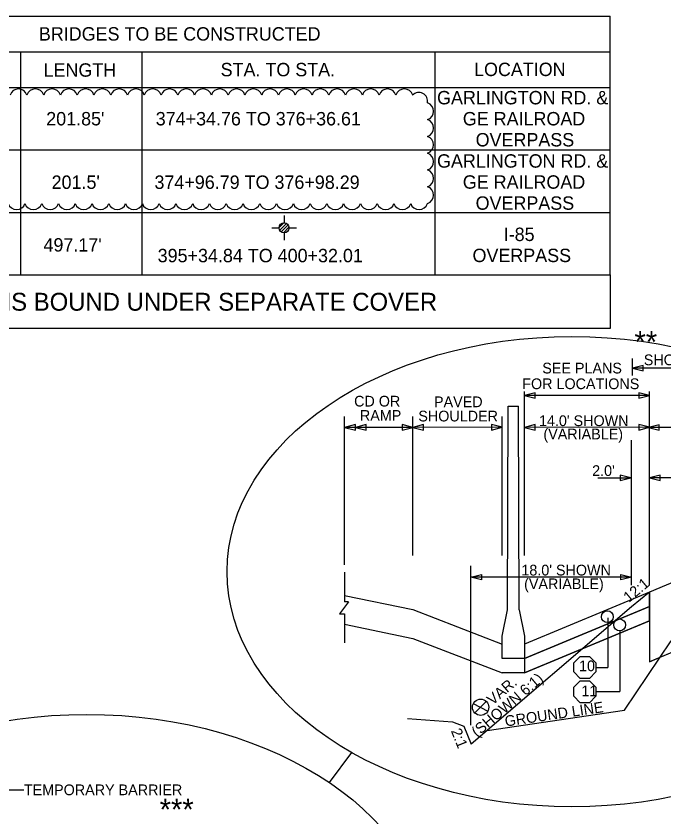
# Model space of a CAD drawing. Extents: x 4832 to 5477, y 4935 to 5220.
# Drawn here: x 5049.2 to 5121.8, y 5127.7 to 5217.4 of the extents above; entities that cross this region are included whole.
import ezdxf

# ---------------------------------------------------------------- set-up
doc = ezdxf.new("R2010")
doc.units = 0
for name, color, linetype in [('Level 2', 7, 'Continuous'), ('Level 3', 7, 'Continuous'), ('Level 42', 7, 'Continuous'), ('RD_EX_SU_Pole', 7, 'Continuous'), ('RD_QTY_Milling', 7, 'Continuous'), ('RD_QTY_Surf_Course', 7, 'Continuous'), ('RD_SHT_TX', 7, 'Continuous'), ('RD_SHT_Typical', 7, 'Continuous'), ('RD_TX_TypSect', 7, 'Continuous'), ('RD_XS_ExGround', 7, 'Continuous'), ('RD_XS_PaveShd', 7, 'Continuous'), ('TERMINATOR', 7, 'Continuous'), ('typical_on', 7, 'Continuous')]:
    doc.layers.add(name, color=color, linetype=linetype)

# ---------------------------------------------------------------- blocks, each defined once
blk = doc.blocks.new('AH')
at = {"layer": 'TERMINATOR'}
blk.add_lwpolyline([(-6, 1.5), (0, 0), (-6, -1.5)], close=True, dxfattribs=at)
blk = doc.blocks.new('SUE_TFP')
at = {"layer": 'RD_EX_SU_Pole'}
for p, q in [((0, 5.5), (0, 2.22)), ((-2.21, 0.13), (-0.13, 2.21)), ((-1.96, -1.03), (1.03, 1.96)), ((-1.31, -1.79), (1.79, 1.31)), ((-0.3, -2.2), (2.2, 0.3)), ((2.22, 0), (5.53, 0.01)), ((-5.53, -0.01), (-2.22, 0)), ((0, -2.22), (0, -5.5))]:
    blk.add_line(p, q, dxfattribs=at)
blk.add_circle((0, 0), 2.22, dxfattribs=at)

msp = doc.modelspace()

# ---------------------------------------------------------------- linework, layer by layer
at = {"layer": 'Level 2'}
for p, q in [((5104.248, 5150.93), (5104.326, 5173.731)), ((5104.326, 5173.731), (5105.471, 5173.731)), ((5105.548, 5150.93), (5105.471, 5173.731)), ((5103.649, 5147.966), (5104.248, 5150.93)), ((5105.548, 5150.93), (5106.148, 5147.967)), ((5103.649, 5145.464), (5103.649, 5147.966)), ((5106.148, 5147.967), (5106.148, 5145.464)), ((5106.148, 5145.464), (5103.649, 5145.464)), ((5106.148, 5143.857), (5103.649, 5143.857))]:
    msp.add_line(p, q, dxfattribs=at)
at = {"layer": 'Level 3'}
for p, q in [((5018.153, 5217.416), (5115.753, 5217.416)), ((5115.753, 5188.416), (5115.753, 5217.416)), ((5018.153, 5213.416), (5115.753, 5213.416)), ((5049.753, 5188.416), (5049.753, 5213.416)), ((5063.353, 5188.416), (5063.353, 5213.416)), ((5096.153, 5188.416), (5096.153, 5213.416)), ((5018.153, 5209.416), (5115.753, 5209.416)), ((5018.153, 5202.416), (5115.753, 5202.416)), ((5018.153, 5195.416), (5115.753, 5195.416)), ((5018.153, 5188.416), (5115.753, 5188.416)), ((5031.753, 5188.416), (5115.753, 5188.416))]:
    msp.add_line(p, q, dxfattribs=at)
at = {"layer": 'Level 42'}
msp.add_lwpolyline([(5018.153, 5188.416), (5115.753, 5188.416), (5115.753, 5182.416), (5018.153, 5182.416)], close=True, dxfattribs=at)
at = {"layer": 'RD_QTY_Milling'}
for p, q in [((5120.142, 5152.902), (5106.148, 5147.071)), ((5120.143, 5151.295), (5120.142, 5152.902)), ((5120.143, 5151.295), (5115.472, 5149.349)), ((5120.143, 5149.689), (5120.143, 5151.295)), ((5115.472, 5149.349), (5106.148, 5145.464)), ((5106.148, 5147.071), (5106.148, 5145.464)), ((5106.148, 5145.464), (5106.148, 5143.857))]:
    msp.add_line(p, q, dxfattribs=at)
for points in [[(5106.148, 5145.464), (5115.472, 5149.349), (5120.143, 5151.295)], [(5106.148, 5143.857), (5116.81, 5148.3), (5120.143, 5149.689)]]:
    msp.add_lwpolyline(points, dxfattribs=at)
at = {"layer": 'RD_QTY_Surf_Course'}
msp.add_line((5086.013, 5152.529), (5093.653, 5150.942), dxfattribs=at)
at = {"layer": 'RD_SHT_TX'}
for centre, radius, start, end in [((5049.495, 5208.266), 0.985, 17.5, 162.5), ((5051.373, 5208.266), 0.985, 17.5, 162.5), ((5053.251, 5208.266), 0.985, 17.5, 162.5), ((5055.129, 5208.266), 0.985, 17.5, 162.5), ((5057.007, 5208.266), 0.985, 17.5, 162.5), ((5058.885, 5208.266), 0.985, 17.5, 162.5), ((5060.764, 5208.266), 0.985, 17.5, 162.5), ((5062.642, 5208.266), 0.985, 17.5, 162.5), ((5064.52, 5208.266), 0.985, 17.5, 162.5), ((5066.398, 5208.266), 0.985, 17.5, 162.5), ((5068.276, 5208.266), 0.985, 17.5, 162.5), ((5070.154, 5208.266), 0.985, 17.5, 162.5), ((5072.032, 5208.266), 0.985, 17.5, 162.5), ((5073.91, 5208.266), 0.985, 17.5, 162.5), ((5075.788, 5208.266), 0.985, 17.5, 162.5), ((5077.666, 5208.266), 0.985, 17.5, 162.5), ((5079.544, 5208.266), 0.985, 17.5, 162.5), ((5081.422, 5208.266), 0.985, 17.5, 162.5), ((5083.3, 5208.266), 0.985, 17.5, 162.5), ((5085.178, 5208.266), 0.985, 17.5, 162.5), ((5087.056, 5208.266), 0.985, 17.5, 162.5), ((5088.935, 5208.266), 0.985, 17.5, 162.5), ((5090.813, 5208.266), 0.985, 17.5, 162.5), ((5092.691, 5208.266), 0.985, 17.5, 162.5), ((5094.323, 5207.863), 0.984, 349.79926, 134.79926), ((5094.996, 5206.75), 0.985, 287.5, 72.5), ((5094.996, 5204.872), 0.985, 287.5, 72.5), ((5094.996, 5202.994), 0.985, 287.5, 72.5), ((5094.996, 5201.116), 0.985, 287.5, 72.5), ((5094.996, 5199.237), 0.985, 287.5, 72.5), ((5094.996, 5197.359), 0.985, 287.5, 72.5), ((5049.279, 5196.716), 0.985, 197.5, 342.5), ((5051.157, 5196.716), 0.985, 197.5, 342.5), ((5053.036, 5196.716), 0.985, 197.5, 342.5), ((5054.914, 5196.716), 0.985, 197.5, 342.5), ((5056.792, 5196.716), 0.985, 197.5, 342.5), ((5058.67, 5196.716), 0.985, 197.5, 342.5), ((5060.548, 5196.716), 0.985, 197.5, 342.5), ((5062.426, 5196.716), 0.985, 197.5, 342.5), ((5064.304, 5196.716), 0.985, 197.5, 342.5), ((5066.182, 5196.716), 0.985, 197.5, 342.5), ((5068.06, 5196.716), 0.985, 197.5, 342.5), ((5069.938, 5196.716), 0.985, 197.5, 342.5), ((5071.816, 5196.716), 0.985, 197.5, 342.5), ((5073.694, 5196.716), 0.985, 197.5, 342.5), ((5075.572, 5196.716), 0.985, 197.5, 342.5), ((5077.45, 5196.716), 0.985, 197.5, 342.5), ((5079.329, 5196.716), 0.985, 197.5, 342.5), ((5081.207, 5196.716), 0.985, 197.5, 342.5), ((5083.085, 5196.716), 0.985, 197.5, 342.5), ((5084.963, 5196.716), 0.985, 197.5, 342.5), ((5086.841, 5196.716), 0.985, 197.5, 342.5), ((5088.719, 5196.716), 0.985, 197.5, 342.5), ((5090.597, 5196.716), 0.985, 197.5, 342.5), ((5092.475, 5196.716), 0.985, 197.5, 342.5), ((5094.353, 5196.716), 0.985, 197.5, 342.5)]:
    msp.add_arc(centre, radius, start, end, dxfattribs=at)
at = {"layer": 'RD_SHT_Typical'}
for p, q in [((5086.012, 5155.126), (5086.013, 5151.806)), ((5120.142, 5152.902), (5118.146, 5151.238)), ((5120.143, 5151.295), (5120.143, 5152.902)), ((5086.449, 5151.806), (5085.441, 5150.46)), ((5086.449, 5151.806), (5086.013, 5151.806)), ((5120.143, 5149.689), (5120.143, 5151.295)), ((5085.441, 5150.46), (5086.013, 5150.46)), ((5086.013, 5150.46), (5086.014, 5147.218)), ((5120.143, 5149.689), (5120.143, 5145.11)), ((5086.014, 5149.31), (5093.653, 5147.715)), ((5130.138, 5149.275), (5120.142, 5145.11)), ((5106.148, 5145.464), (5106.148, 5143.858))]:
    msp.add_line(p, q, dxfattribs=at)
at = {"layer": 'RD_TX_TypSect'}
for p, q in [((5118.238, 5177.155), (5118.238, 5179.068)), ((5130.234, 5177.967), (5118.238, 5177.967)), ((5106.148, 5157.012), (5106.148, 5175.38)), ((5120.142, 5174.905), (5106.148, 5174.904)), ((5120.142, 5153.687), (5120.142, 5175.38)), ((5086.013, 5155.952), (5086.013, 5172.58)), ((5093.653, 5157.012), (5093.653, 5172.58)), ((5103.649, 5157.012), (5103.649, 5172.58)), ((5093.653, 5171.353), (5086.013, 5171.353)), ((5103.649, 5171.354), (5093.653, 5171.353)), ((5120.142, 5171.354), (5106.148, 5171.353)), ((5130.03, 5171.331), (5120.047, 5171.331)), ((5118.143, 5153.687), (5118.143, 5169.905)), ((5114.382, 5165.696), (5118.059, 5165.696)), ((5124.154, 5165.696), (5120.156, 5165.696)), ((5130.239, 5157.109), (5120.142, 5152.902)), ((5100.15, 5137.993), (5100.15, 5155.849)), ((5118.143, 5154.575), (5100.15, 5154.575)), ((5120.142, 5152.902), (5120.143, 5151.295)), ((5120.143, 5151.295), (5120.143, 5149.689)), ((5115.472, 5150.03), (5115.472, 5144.444)), ((5120.143, 5149.689), (5120.143, 5145.11)), ((5116.81, 5148.564), (5116.81, 5141.767)), ((5114.139, 5144.444), (5115.472, 5144.444)), ((5114.139, 5141.767), (5116.81, 5141.767)), ((5100.607, 5139.362), (5101.866, 5140.646)), ((5100.42, 5140.418), (5102.053, 5139.585)), ((5084.304, 5131.579), (5086.801, 5134.928)), ((5047.966, 5130.758), (5050.077, 5130.758))]:
    msp.add_line(p, q, dxfattribs=at)
msp.add_lwpolyline([(5120.143, 5145.11), (5121.344, 5145.611), (5130.138, 5149.275)], dxfattribs=at)
for centre, radius in [((5115.433, 5150.146), 0.666), ((5116.81, 5149.23), 0.666), ((5101.242, 5140.007), 0.913)]:
    msp.add_circle(centre, radius, dxfattribs=at)
for centre in [(5111.468, 5155.19), (5057.119, 5112.876)]:
    msp.add_ellipse(centre, major_axis=(38.618, 0), ratio=0.681891, dxfattribs=at)
at = {"layer": 'RD_XS_ExGround'}
for p, q in [((5118.146, 5151.238), (5100.18, 5135.871)), ((5117.333, 5139.673), (5122.573, 5147.429)), ((5101.984, 5137.413), (5117.333, 5139.673)), ((5093.04, 5138.738), (5098.092, 5138.377)), ((5098.092, 5138.377), (5099.369, 5137.9)), ((5099.369, 5137.9), (5100.18, 5135.871))]:
    msp.add_line(p, q, dxfattribs=at)
at = {"layer": 'RD_XS_PaveShd'}
for p, q in [((5130.239, 5157.109), (5120.142, 5152.902)), ((5120.142, 5152.902), (5106.148, 5147.071)), ((5093.653, 5150.942), (5103.649, 5147.071)), ((5120.142, 5151.295), (5106.148, 5145.464)), ((5120.143, 5149.689), (5106.148, 5143.858)), ((5093.653, 5147.715), (5103.649, 5143.844)), ((5106.148, 5147.071), (5106.148, 5145.464))]:
    msp.add_line(p, q, dxfattribs=at)
at = {"layer": 'typical_on'}
for points in [[(5114.139, 5144.974), (5114.139, 5143.954), (5113.418, 5143.233), (5112.398, 5143.233), (5111.677, 5143.954), (5111.677, 5144.974), (5112.398, 5145.695), (5113.418, 5145.695)], [(5114.139, 5142.251), (5114.139, 5141.232), (5113.418, 5140.511), (5112.398, 5140.51), (5111.677, 5141.231), (5111.677, 5142.251), (5112.398, 5142.972), (5113.418, 5142.972)]]:
    msp.add_lwpolyline(points, close=True, dxfattribs=at)

# ---------------------------------------------------------------- block references
at = {"layer": 'Level 3', "xscale": 0.24999999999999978, "yscale": 0.24999999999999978}
msp.add_blockref('SUE_TFP', (5079.232, 5193.695), dxfattribs=at)
at = {"layer": 'TERMINATOR'}
for p, xscale, yscale, rotation in [((5118.238, 5177.967), 0.2000217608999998, -0.20002176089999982, -179.998582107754), ((5106.148, 5174.904), 0.2000217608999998, -0.20002176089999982, -179.998582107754), ((5120.142, 5174.905), 0.2000217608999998, -0.20002176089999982, 0.0014178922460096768), ((5086.013, 5171.353), 0.2000217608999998, -0.20002176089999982, -179.998582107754), ((5087.213, 5171.353), 0.2000217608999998, -0.20002176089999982, -179.998582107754), ((5093.653, 5171.353), 0.2000217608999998, -0.20002176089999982, 0.0014178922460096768), ((5093.653, 5171.353), 0.2000217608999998, -0.20002176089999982, -179.998582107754), ((5103.649, 5171.354), 0.2000217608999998, -0.20002176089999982, 0.0014178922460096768), ((5106.148, 5171.353), 0.2000217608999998, -0.20002176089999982, -179.998582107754), ((5120.142, 5171.354), 0.2000217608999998, -0.20002176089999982, 0.0014178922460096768), ((5120.047, 5171.331), 0.2000217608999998, -0.20002176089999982, -179.998582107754), ((5118.059, 5165.696), 0.2000217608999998, -0.20002176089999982, 0.0014178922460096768), ((5120.156, 5165.696), 0.2000217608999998, -0.20002176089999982, -179.998582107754), ((5100.15, 5154.575), 0.19992179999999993, 0.19992179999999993, -179.99858210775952), ((5118.143, 5154.575), 0.19992179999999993, 0.19992179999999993, 0.0014178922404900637)]:
    msp.add_blockref('AH', p, dxfattribs=dict(at, xscale=xscale, yscale=yscale, rotation=rotation))

# ---------------------------------------------------------------- texts
at = {"layer": 'Level 3'}
for s, height, p in [('BRIDGES TO BE CONSTRUCTED', 1.5, (5051.776, 5214.666)), ('LENGTH', 1.5, (5052.302, 5210.619)), ('STA. TO STA.', 1.5, (5072.129, 5210.666)), ('LOCATION', 1.5, (5100.503, 5210.691)), ('GARLINGTON RD. & ', 1.5, (5096.362, 5207.523)), ("201.85'", 1.5, (5052.598, 5205.166)), ('374+34.76 TO 376+36.61', 1.5, (5064.859, 5205.166)), ('GE RAILROAD', 1.5, (5099.247, 5205.166)), ('OVERPASS', 1.5, (5100.682, 5202.809)), ('GARLINGTON RD. & ', 1.5, (5096.359, 5200.433)), ("201.5'", 1.5, (5053.2, 5198.056)), ('374+96.79 TO 376+98.29', 1.5, (5064.718, 5198.056)), ('GE RAILROAD', 1.5, (5099.244, 5198.076)), ('OVERPASS', 1.5, (5100.678, 5195.719)), ('I-85 ', 1.5, (5103.827, 5192.215)), ("497.17'", 1.5, (5052.291, 5191.037)), ('395+34.84 TO 400+32.01', 1.5, (5065.078, 5189.841)), ('OVERPASS', 1.5, (5100.331, 5189.858)), ('BRIDGE PLANS BOUND UNDER SEPARATE COVER', 2, (5030.689, 5184.416))]:
    msp.add_text(s, height=height, rotation=360, dxfattribs=at).set_placement(p)
at = {"layer": 'RD_TX_TypSect'}
for s, height, p in [('**', 2.4431, (5118.463, 5179.696)), ('SHOULDER', 1.2, (5119.508, 5178.311)), ('SEE PLANS', 1.2, (5108.143, 5177.386)), ('FOR LOCATIONS', 1.2, (5105.904, 5175.63)), ('CD OR', 1.2, (5087.072, 5173.682)), ('PAVED', 1.2, (5096.022, 5173.611)), ('RAMP', 1.2, (5087.724, 5172.085)), ('SHOULDER', 1.2, (5094.264, 5172.014)), ("14.0' SHOWN", 1.2, (5107.774, 5171.494)), ('(VARIABLE)', 1.2, (5108.27, 5170.006)), ('(VARIABLE)', 1.2, (5106.108, 5153.234)), ('10', 1.2, (5112.26, 5144.039)), ('11', 1.2, (5112.525, 5141.232)), ('TEMPORARY BARRIER', 1.2, (5050.092, 5130.158)), ('***', 2.4431, (5065.296, 5127.337))]:
    msp.add_text(s, height=height, dxfattribs=at).set_placement(p)
for s, rotation, p in [("2.0'", 359.99858, (5113.726, 5165.908)), ("18.0' SHOWN", 0.00071, (5105.802, 5154.763)), ('12:1', 39.80557, (5117.845, 5151.677)), ('(SHOWN 6:1)', 40.54218, (5100.847, 5136.595)), ('VAR.', 40.54218, (5102.581, 5140.179)), ('GROUND LINE', 8.37565, (5104.037, 5137.837)), ('2:1', 291.80141, (5097.896, 5137.362))]:
    msp.add_text(s, height=1.2, rotation=rotation, dxfattribs=at).set_placement(p)

doc.saveas('drawing.dxf')
